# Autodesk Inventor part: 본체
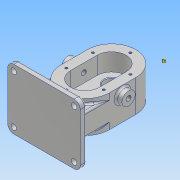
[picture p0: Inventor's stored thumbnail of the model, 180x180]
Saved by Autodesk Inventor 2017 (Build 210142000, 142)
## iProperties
Part Number: 본체
Material: 알루미늄 6061
Document SubType Name: Modeling
Designer: 222
Density: 2.7 g/cm^3
Appearance: 알루미늄 - 평지
Mass: 1442.14 g
Surface Area: 789.865 cm^2
Volume: 534.127 cm^3
Author: 222
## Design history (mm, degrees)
sketch "스케치1"
  geometry: L1 (-40, 0)-(-40, -44); L2 (40, 0)-(40, -44); A1 r 40 centre (0, 0) between (40, 0) and (-40, 0); A2 r 40 centre (0, -44) between (-40, -44) and (40, -44); 1 further point
  constraints: 4 end point, 4 point on circle, 4 tangent, 2 centre point, 1 coincident, 1 vertical alignment
  dimensions: "d7" = 80 diameter of A2; "d8" = 80 diameter of A1; "d9" = 124 dimension on A2 A1
extrude "돌출1" new body sketch "스케치1" distance "d10" = 53; taper "d11" = 0 deg
sketch "스케치2"
  geometry: L1 (-24, 0)-(-24, -44); L2 (24, 0)-(24, -44); A1 r 24 centre (0, 0) between (24, 0) and (-24, 0); A2 r 24 centre (0, -44) between (-24, -44) and (24, -44); 1 further point
  constraints: 4 end point, 4 point on circle, 3 tangent, 2 centre point, 1 coincident, 1 vertical, 1 vertical alignment
  dimensions: "d12" = 48 diameter of A1; "d13" = 48 diameter of A2; "d14" = 92 dimension on A2 A1
extrude "돌출2" cut sketch "스케치2" distance "d15" = 29; taper "d16" = 0 deg
node "작업 평면1"
sketch "스케치4"
  geometry: C1 r 19 at (0, 0); 1 further point
  constraints: 1 centre point, 1 coincident
  dimensions: "d18" = 38 diameter of C1
extrude "돌출3" join sketch "스케치4" distance "d19" = 17; taper "d20" = 0 deg
sketch "스케치5"
  geometry: C1 r 12.5 at (0, 0); 1 further point
  constraints: 1 centre point, 1 coincident
  dimensions: "d21" = 25 diameter of C1
extrude "돌출4" cut sketch "스케치5" distance "d22" = 15; taper "d23" = 0 deg
sketch "스케치6"
  geometry: C1 r 8.5 at (0, 0); 1 further point
  constraints: 1 centre point, 1 coincident
  dimensions: "d24" = 17 diameter of C1
extrude "돌출5" cut sketch "스케치6" stored distance "d25" = 15; taper "d26" = 0 deg
sketch "스케치7"
  geometry: L1 (24, 0)-(24, -44) reference; L2 (-24, -44)-(-24, 0) reference; L3 (-40, 0)-(-40, -44) reference; L4 (40, -44)-(40, 0) reference; C1 r 12.5 at (0, -44); A1 r 24 centre (0, 0) between (24, 0) and (-24, 0) reference; A2 r 24 centre (0, -44) between (-24, -44) and (24, -44) reference; A3 r 40 centre (0, 0) between (40, 0) and (-40, 0) reference; A4 r 40 centre (0, -44) between (-40, -44) and (40, -44) reference; 1 further point
  constraints: 1 centre point, 1 coincident
  dimensions: "d27" = 25 diameter of C1
extrude "돌출6" cut sketch "스케치7" distance "d28" = 15; taper "d29" = 0 deg
sketch "스케치8"
  geometry: C1 r 14 at (0, 0); 1 further point
  constraints: 1 centre point, 1 coincident
  dimensions: "d30" = 28 diameter of C1
extrude "돌출7" cut sketch "스케치8" distance "d31" = 7.3; taper "d32" = 0 deg
node "작업 평면3"
  node "작업 평면2"
sketch "스케치9"
  geometry: L1 (60, 83)-(-60, 83); L2 (-60, 83)-(-60, -17); L3 (-60, -17)-(60, -17); L4 (60, -17)-(60, 83); L5 (-19, -17)-(19, -17) reference; 3 further points
  constraints: 8 end point, 3 midpoint, 2 parallel, 1 coincident, 1 horizontal, 1 perpendicular
  dimensions: "d34" = 120 distance of L3.end L2.end; "d35" = 100 distance of L2.end L1.end
extrude "돌출8" join sketch "스케치9" distance "d36" = 10; taper "d37" = 0 deg
sketch "스케치10"
  geometry: L1 (-40, -45)-(40, -45); L2 (40, -45)-(40, -8); L3 (40, -8)-(-40, -8); L4 (-40, -8)-(-40, -45); L5 (60, 17)-(-60, 17) reference; 3 further points
  constraints: 8 end point, 2 coincident, 2 parallel, 1 horizontal, 1 midpoint, 1 perpendicular, 1 vertical alignment
  dimensions: "d40" = 80 distance of L3.end L2.end; "d41" = 37 distance of L2.end L1.end; "d42" = 25 distance between parallel lines of L5 L3
extrude "돌출9" join sketch "스케치10" stored distance "d43" = 10; taper "d44" = 0 deg
fillet "모깎기1" dims "d45" = 10
sketch "스케치11"
  geometry: L1 (0, 44)-(-53, 44) reference; L2 (-53, 0)-(-53, 44) reference; L3 (-45, 0)-(-53, 0) reference; L4 (-45, -58)-(-45, 0) reference; L5 (-83, -58)-(-45, -58) reference; L6 (-83, -68)-(-83, -58) reference; L7 (17, -68)-(-83, -68) reference; L8 (17, -58)-(17, -68) reference; L9 (-8, -58)-(17, -58) reference; L10 (-45, -58)-(-8, -58) reference; L11 (0, 44)-(0, 0) reference; L12 (0, 0)-(-8, 0) reference; L13 (-8, 0)-(-8, -58) reference; C1 r 11 at (-39, 22)
  constraints: 1 centre point
  dimensions: "d46" = 22 diameter of C1; "d47" = 22 distance from line of C1.centre L1; "d48" = 14 distance from line of L2 C1.centre
extrude "돌출10" join sketch "스케치11" distance "d49" = 10; taper "d50" = 0 deg
sketch "스케치12"
  geometry: C1 r 11 at (0, 0) reference; 2 further points
  constraints: 1 coincident
hole "구멍1" sketch "스케치12" at (0, 0) diameter "d51" = 8.376; stored, may be unused: countersink angle "d55" = 90 deg, drill point angle "d57" = 0 deg; dims "d52" = 20, "d53" = 25, "d54" = 15, "d56" = 27.3
sketch "스케치13" dims "d58" = 62
  geometry: L1 (0, 0)-(0, 31); C1 r 30.5 at (0, -44); A1 r 40 centre (0, -44) between (-40, -44) and (40, -44) reference; 2 further points
  constraints: 3 coincident, 2 end point, 1 centre point, 1 vertical, 1 vertical alignment, 2 other
  dimensions: "d59" = 61 diameter of C1
hole "구멍2" sketch "스케치13" at (0, 31) diameter "d60" = 4.134; stored, may be unused: countersink angle "d64" = 90 deg, drill point angle "d66" = 118 deg; dims "d61" = 10, "d62" = 25, "d63" = 15, "d65" = 12
sketch "스케치14" dims "d70" = 62
  geometry: L1 (0, -44)-(0, -75); A1 r 40 centre (0, -44) between (-40, -44) and (40, -44) reference; 2 further points
  constraints: 2 coincident, 2 end point, 1 vertical, 1 vertical alignment, 2 other
hole "구멍3" sketch "스케치14" at (0, -75) diameter "d71" = 4.134; stored, may be unused: countersink angle "d75" = 90 deg, drill point angle "d77" = 118 deg; dims "d72" = 10, "d73" = 25, "d74" = 15, "d76" = 12
sketch "스케치15"
  geometry: C1 r 4.5 at (-50, -73); C2 r 4.5 at (-50, 7); C3 r 4.5 at (50, 7); C4 r 4.5 at (50, -73); A1 r 10 centre (-50, 7) between (-50, 17) and (-60, 7) reference; A2 r 10 centre (-50, -73) between (-60, -73) and (-50, -83) reference; A3 r 10 centre (50, -73) between (50, -83) and (60, -73) reference; A4 r 10 centre (50, 7) between (60, 7) and (50, 17) reference; 1 further point
  constraints: 4 centre point, 4 coincident
  dimensions: "d81" = 9 diameter of C1; "d82" = 9 diameter of C2; "d83" = 9 diameter of C3; "d84" = 9 diameter of C4
extrude "돌출11" cut sketch "스케치15" stored distance "d85" = 10; taper "d86" = 0 deg
sketch "스케치16"
  geometry: L1 (-50, 17)-(50, 17) reference; L2 (60, 7)-(60, -73) reference; L3 (50, -83)-(-50, -83) reference; L4 (-60, -73)-(-60, 7) reference; L5 (-40, -45)-(-40, -8) reference; L6 (-40, -8)-(40, -8) reference; L7 (40, -8)-(40, -45) reference; L8 (40, -45)-(-40, -45) reference; C1 r 4.5 at (50, 7) reference; C2 r 4.5 at (-50, -73) reference; C3 r 4.5 at (-50, 7) reference; C4 r 4.5 at (50, -73) reference; A1 r 10 centre (-50, 7) between (-50, 17) and (-60, 7) reference; A2 r 10 centre (50, 7) between (60, 7) and (50, 17) reference; A3 r 10 centre (50, -73) between (50, -83) and (60, -73) reference; A4 r 10 centre (-50, -73) between (-60, -73) and (-50, -83) reference; 2 further points
  constraints: 1 other
  dimensions: "d87" = 60 distance from line of point (0, -71) L4; "d88" = 12 distance from line of L3 point (0, -71)
feature "엠보싱1" sketch "스케치16" dims "d7" = 80, "d19" = 17, "d89" = 0.5, "d90" = 0
fillet "모깎기2" dims "d94" = 0.5
chamfer "모따기2" distance "d95" = 0.4; stored, may be unused: second distance "d96" = 2, angle "d97" = 60 deg
fillet "모깎기3" dims "d98" = 3
fillet "모깎기4" dims "d99" = 3
fillet "모깎기5" dims "d100" = 3
fillet "모깎기6" dims "d101" = 3
chamfer "모따기3" distance "d102" = 1; stored, may be unused: second distance "d103" = 2, angle "d104" = 30 deg
chamfer "모따기4" distance "d105" = 1; stored, may be unused: second distance "d106" = 2, angle "d107" = 45 deg
node "솔리드1"
mirror "미러1"
mirror "미러2"
pattern_circular "원형 패턴1" dims angle "d68" = 360 deg
pattern_circular "원형 패턴2" dims angle "d79" = 360 deg
node "투영된 루프1"
node "작업 평면4"
node "절단 모서리 투영1"
node "절단 모서리 투영2"
other parameters: "d17" = 17, "d33" = -152
